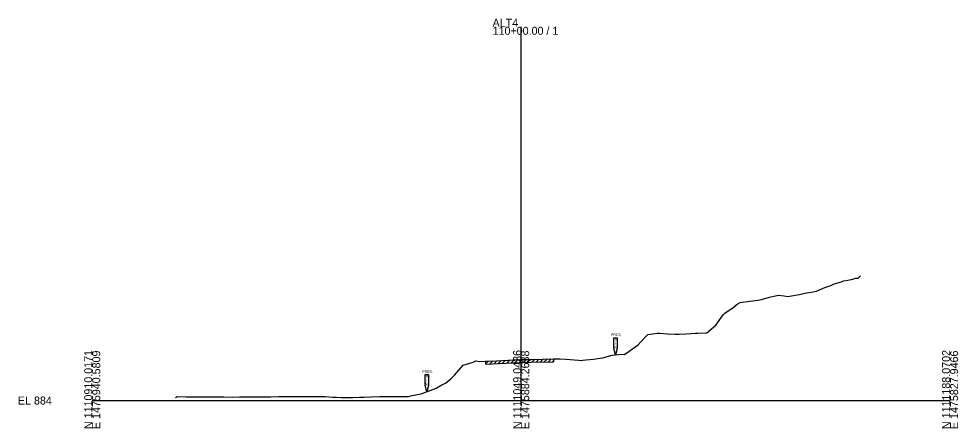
# Model space of a CAD drawing. Extents: x -26 to 1303, y -10 to 19562.
# Drawn here: x 974.3 to 1302.8, y 6490.3 to 6633.6 of the extents above; entities that cross this region are included whole.
import ezdxf

# ---------------------------------------------------------------- set-up
doc = ezdxf.new("R2010")
doc.units = 0
for name, color, linetype in [('RD_GPK_XS_Cell', 7, 'Continuous'), ('RD_XS_ExGround', 7, 'Continuous'), ('RD_XS_ExPaveRet', 7, 'Continuous'), ('RD_XS_ExRW', 7, 'Continuous'), ('RD_XS_TX_Elev_EX', 7, 'Continuous')]:
    doc.layers.add(name, color=color, linetype=linetype)

msp = doc.modelspace()

# ---------------------------------------------------------------- linework, layer by layer
at = {"layer": 'RD_GPK_XS_Cell'}
for p, q in [((1150, 6500), (1150, 6630.8)), ((1000, 6500), (1150, 6500)), ((1150, 6500), (1300, 6500))]:
    msp.add_line(p, q, dxfattribs=at)
at = {"layer": 'RD_XS_ExGround'}
msp.add_lwpolyline([(1029.08, 6501.11), (1029.75, 6501.38), (1032.89, 6501.33), (1035.19, 6501.29), (1036.13, 6501.26), (1037.5, 6501.27), (1038.83, 6501.29), (1039.36, 6501.32), (1040.63, 6501.31), (1042.6, 6501.34), (1045.49, 6501.29), (1046.07, 6501.28), (1049.07, 6501.22), (1051.51, 6501.28), (1052.31, 6501.27), (1053.49, 6501.3), (1054.95, 6501.31), (1055.55, 6501.28), (1056.95, 6501.28), (1058.78, 6501.24), (1059.56, 6501.25), (1061.48, 6501.24), (1062.02, 6501.25), (1062.39, 6501.26), (1065.26, 6501.45), (1067.83, 6501.46), (1068.49, 6501.45), (1069.47, 6501.46), (1071.73, 6501.44), (1073.27, 6501.43), (1074.97, 6501.4), (1075.68, 6501.41), (1077.46, 6501.42), (1078.2, 6501.42), (1078.71, 6501.4), (1081.44, 6501.36), (1084.15, 6501.22), (1084.9, 6501.18), (1085.45, 6501.16), (1087.2, 6501.07), (1087.91, 6501.05), (1089.59, 6501.04), (1091.15, 6501.02), (1093.44, 6501.15), (1094.39, 6501.21), (1095.04, 6501.23), (1097.62, 6501.34), (1100.48, 6501.38), (1100.86, 6501.38), (1101.43, 6501.39), (1104.1, 6501.43), (1105.92, 6501.39), (1107.34, 6501.36), (1109.42, 6501.41), (1110.57, 6501.46), (1111.24, 6501.6), (1115.05, 6502.29), (1118.22, 6503.52), (1120.28, 6504.28), (1122.24, 6505.45), (1123.52, 6506.02), (1125.4, 6507.65), (1126.36, 6508.47), (1126.74, 6508.84), (1129.72, 6512.41), (1133.26, 6513.48), (1134.2, 6513.87), (1135.52, 6513.68), (1137.57, 6513.73), (1141.42, 6513.93), (1149.48, 6514.34), (1150, 6514.35), (1153.48, 6514.41), (1161.25, 6514.55), (1163.63, 6514.55), (1165.6, 6514.48), (1170, 6514.16), (1171.05, 6514.05), (1171.58, 6514.1), (1172.66, 6514.27), (1175.31, 6514.44), (1176.65, 6514.68), (1178.54, 6514.98), (1181.33, 6515.74), (1181.78, 6515.84), (1185.07, 6516.18), (1186.15, 6516.12), (1187.29, 6516.92), (1190.87, 6519.44), (1191.9, 6520.53), (1194.3, 6523.15), (1197.61, 6523.54), (1197.97, 6523.57), (1198.41, 6523.56), (1201.2, 6523.35), (1203.85, 6523.26), (1204.44, 6523.25), (1205.3, 6523.25), (1207.68, 6523.3), (1209.29, 6523.42), (1210.91, 6523.54), (1211.75, 6523.57), (1214.93, 6523.65), (1218.03, 6526.4), (1220.62, 6529.99), (1221.26, 6530.61), (1224.11, 6532.51), (1225.54, 6533.73), (1226.62, 6534.26), (1229.93, 6534.72), (1231.05, 6534.93), (1233.57, 6535.19), (1236.49, 6536.09), (1236.81, 6536.17), (1237.27, 6536.33), (1240.04, 6536.92), (1241.94, 6536.69), (1243.28, 6536.46), (1243.85, 6536.47), (1245.26, 6536.72), (1246.52, 6537.02), (1247.38, 6537.16), (1249.75, 6537.65), (1250.76, 6537.84), (1253.25, 6538.29), (1256.23, 6539.5), (1258.26, 6540.31), (1259.46, 6540.82), (1261.24, 6541.36), (1262.28, 6541.69), (1262.7, 6541.84), (1263.7, 6542.03), (1265.94, 6542.53), (1266.89, 6542.82), (1267.84, 6542.86), (1268.23, 6543.15), (1268.63, 6543.6)], dxfattribs=at)
at = {"layer": 'RD_XS_ExPaveRet'}
for p, q in [((1137.57, 6512.79), (1138.56, 6513.78)), ((1137.57, 6513.73), (1137.57, 6512.73)), ((1139.01, 6512.81), (1140.05, 6513.86)), ((1140.5, 6512.89), (1141.54, 6513.93)), ((1141.98, 6512.96), (1143.03, 6514.01)), ((1143.47, 6513.04), (1144.52, 6514.09)), ((1144.96, 6513.11), (1146.01, 6514.16)), ((1146.45, 6513.19), (1147.5, 6514.24)), ((1147.94, 6513.26), (1148.99, 6514.31)), ((1149.43, 6513.34), (1150.45, 6514.35)), ((1150.88, 6513.37), (1151.89, 6514.38)), ((1152.32, 6513.39), (1153.33, 6514.41)), ((1153.76, 6513.42), (1154.77, 6514.43)), ((1155.2, 6513.45), (1156.21, 6514.46)), ((1156.64, 6513.47), (1157.65, 6514.49)), ((1158.08, 6513.5), (1159.09, 6514.51)), ((1159.52, 6513.53), (1160.54, 6514.54)), ((1160.96, 6513.55), (1161.25, 6513.84)), ((1161.25, 6514.55), (1161.25, 6513.55))]:
    msp.add_line(p, q, dxfattribs=at)
msp.add_lwpolyline([(1137.57, 6512.74), (1149.52, 6513.34), (1153.5, 6513.42), (1161.25, 6513.56)], dxfattribs=at)
at = {"layer": 'RD_XS_ExRW'}
for points in [[(1182.45, 6521.98), (1183.55, 6521.98), (1183.55, 6518.15), (1183, 6515.97), (1182.45, 6518.15)], [(1116.45, 6509.06), (1117.55, 6509.06), (1117.55, 6505.23), (1117, 6503.05), (1116.45, 6505.23)]]:
    msp.add_lwpolyline(points, close=True, dxfattribs=at)

# ---------------------------------------------------------------- texts
at = {"layer": 'RD_GPK_XS_Cell'}
for s, p in [('ALT4', (1140, 6630.8)), ('110+00.00 / 1', (1140, 6628)), ('EL 884', (974, 6498.6))]:
    msp.add_text(s, height=2.8, dxfattribs=at).set_placement(p)
for s, p in [('N 1110910.0171', (1000, 6490)), ('E 1475940.5809', (1002.8, 6490)), ('N 1111049.0436', (1150, 6490)), ('E 1475884.2638', (1152.8, 6490)), ('N 1111188.0702', (1300, 6490)), ('E 1475827.9466', (1302.8, 6490))]:
    msp.add_text(s, height=2.8, rotation=90, dxfattribs=at).set_placement(p)
at = {"layer": 'RD_XS_ExRW'}
for s, p in [('PRES.', (1181.45, 6522.61)), ('R', (1182.71, 6520.89)), ('W', (1182.53, 6518.26)), ('/', (1182.83, 6519.58)), ('PRES.', (1115.45, 6509.69)), ('R', (1116.71, 6507.97)), ('W', (1116.53, 6505.35)), ('/', (1116.83, 6506.66))]:
    msp.add_text(s, height=0.875, dxfattribs=at).set_placement(p)
at = {"layer": 'RD_XS_TX_Elev_EX'}
msp.add_text('898.35', height=0.5, dxfattribs=at).set_placement((1148.98, 6513.85))

doc.saveas('drawing.dxf')
